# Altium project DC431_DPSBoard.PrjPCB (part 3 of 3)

## Sheet DC431_PowerStage.SchDoc
size 558 x 431 mm; Date: Not shown in title block; ApprovedBy: Not shown in title block; CheckedBy: Not shown in title block; Author: Not shown in title block; CompanyName: Not shown in title block; Engineer: Not shown in title block; Organization: Not shown in title block; Address1: Not shown in title block; Address2: Not shown in title block; Address3: Not shown in title block; Address4: Not shown in title block; DocumentNumber: 1; Revision: Use project parameter SCH_Rev; SheetNumber: 3; SheetTotal: 9; PageSetup: Record=PageOptions¦CenterHorizontal=True¦CenterVertical=True¦PrintScale=1.00¦XCorrection=1.00¦YCorrection=1.00¦PrintKind=0¦BorderSize=5000000¦LeftOffset=0¦BottomOffset=0¦Orientation=2¦PaperLength=1000¦PaperWidth=1000¦Scale=100¦PaperSource=15¦PrintQuality=600¦MediaType=1¦DitherType=10¦PaperKind=Letter¦PrintScaleMode=1
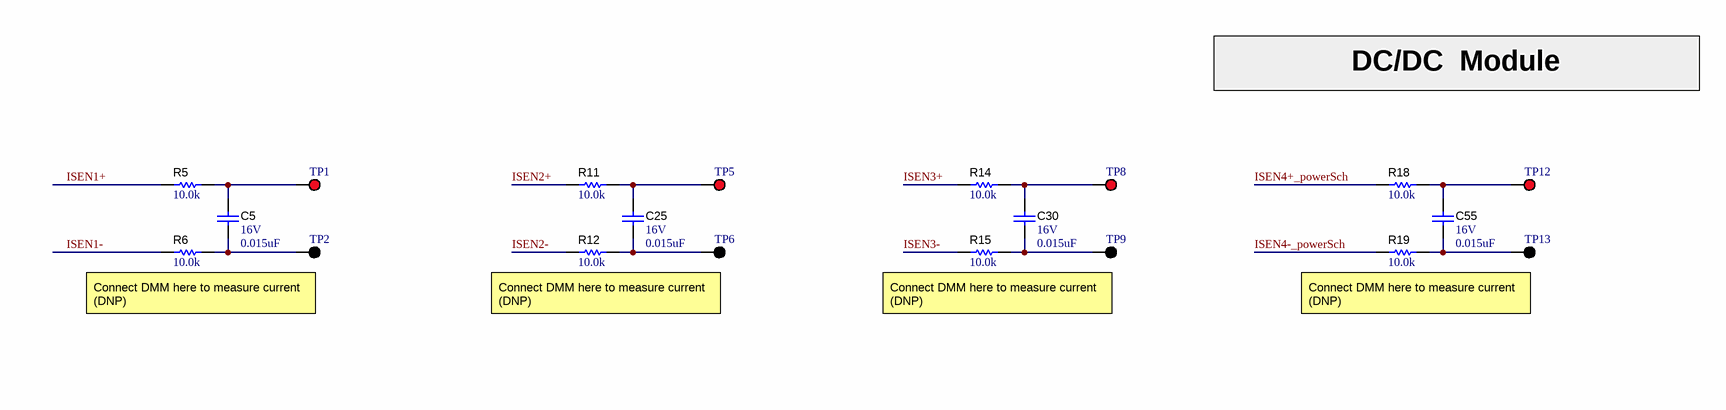
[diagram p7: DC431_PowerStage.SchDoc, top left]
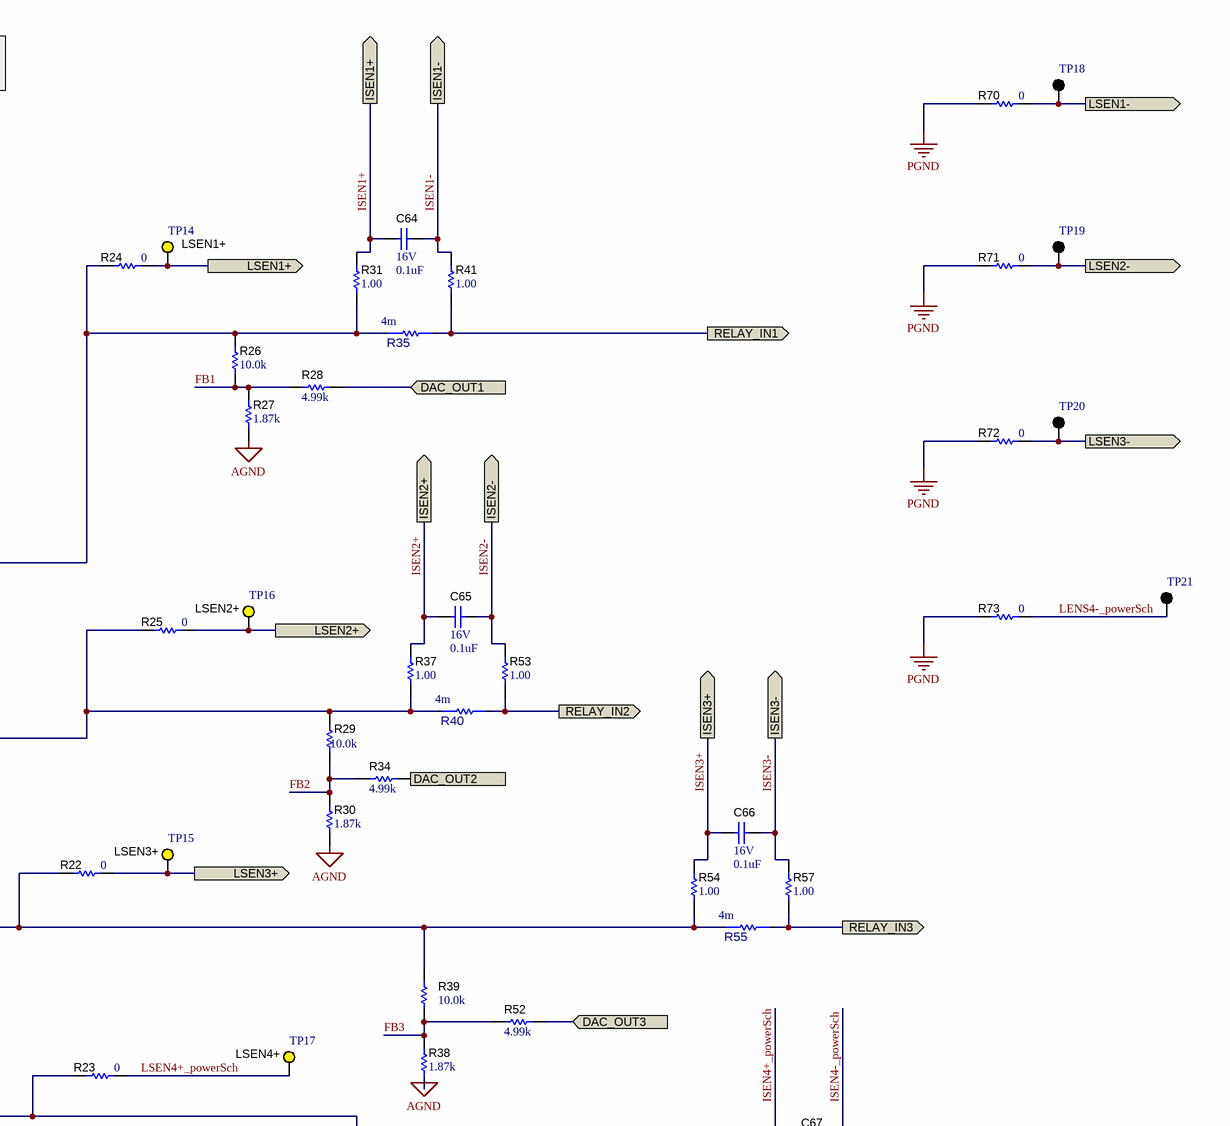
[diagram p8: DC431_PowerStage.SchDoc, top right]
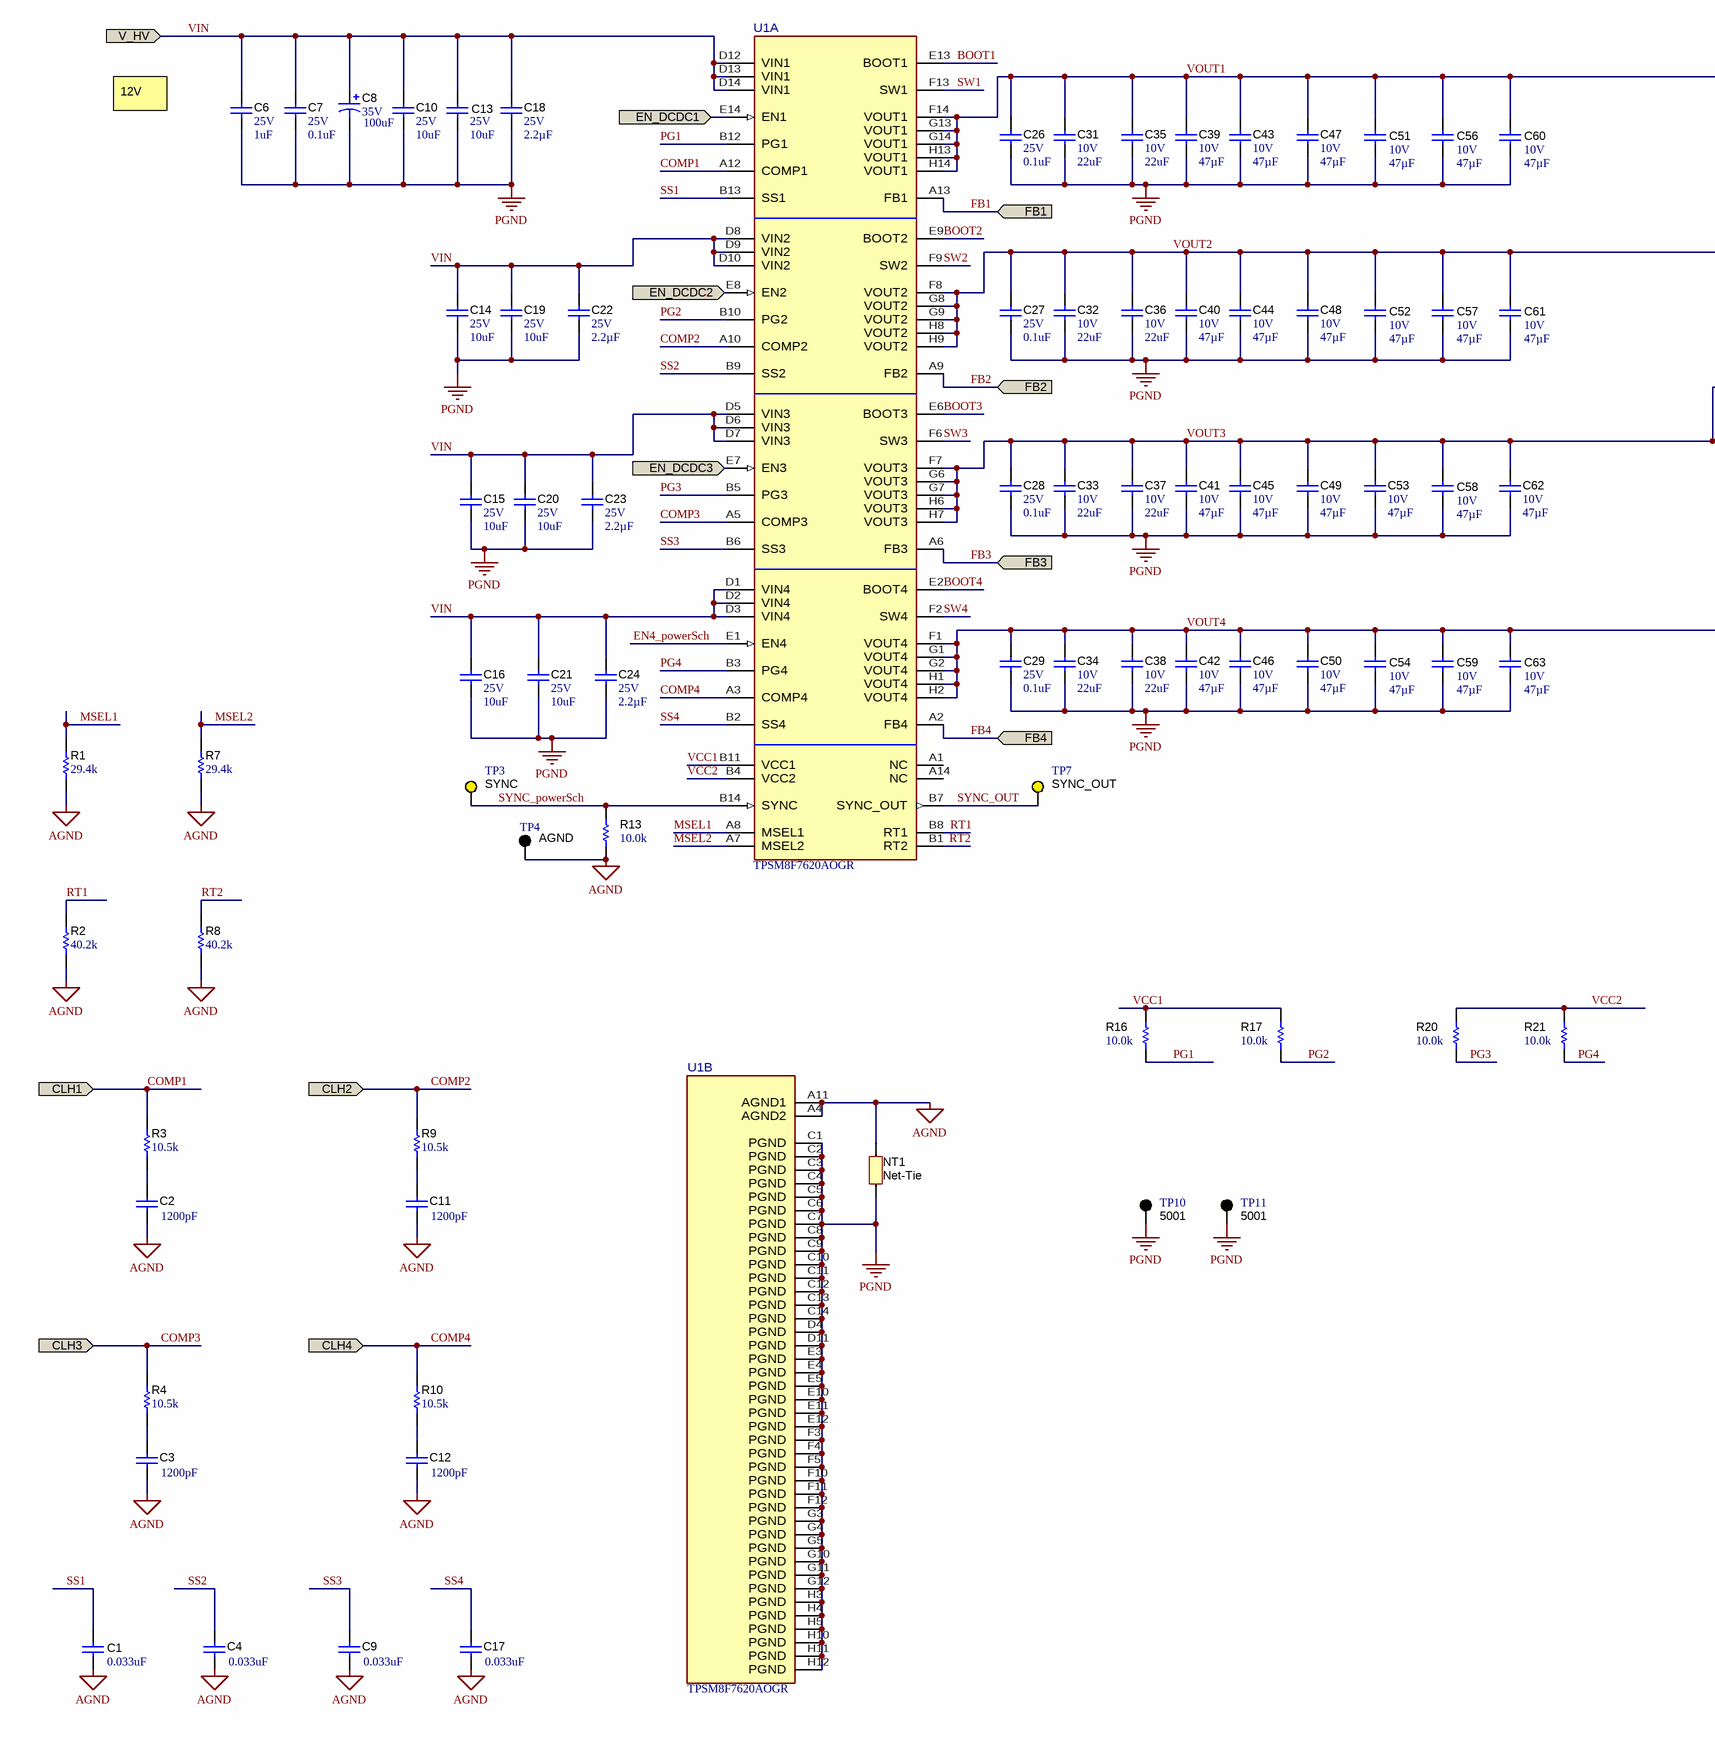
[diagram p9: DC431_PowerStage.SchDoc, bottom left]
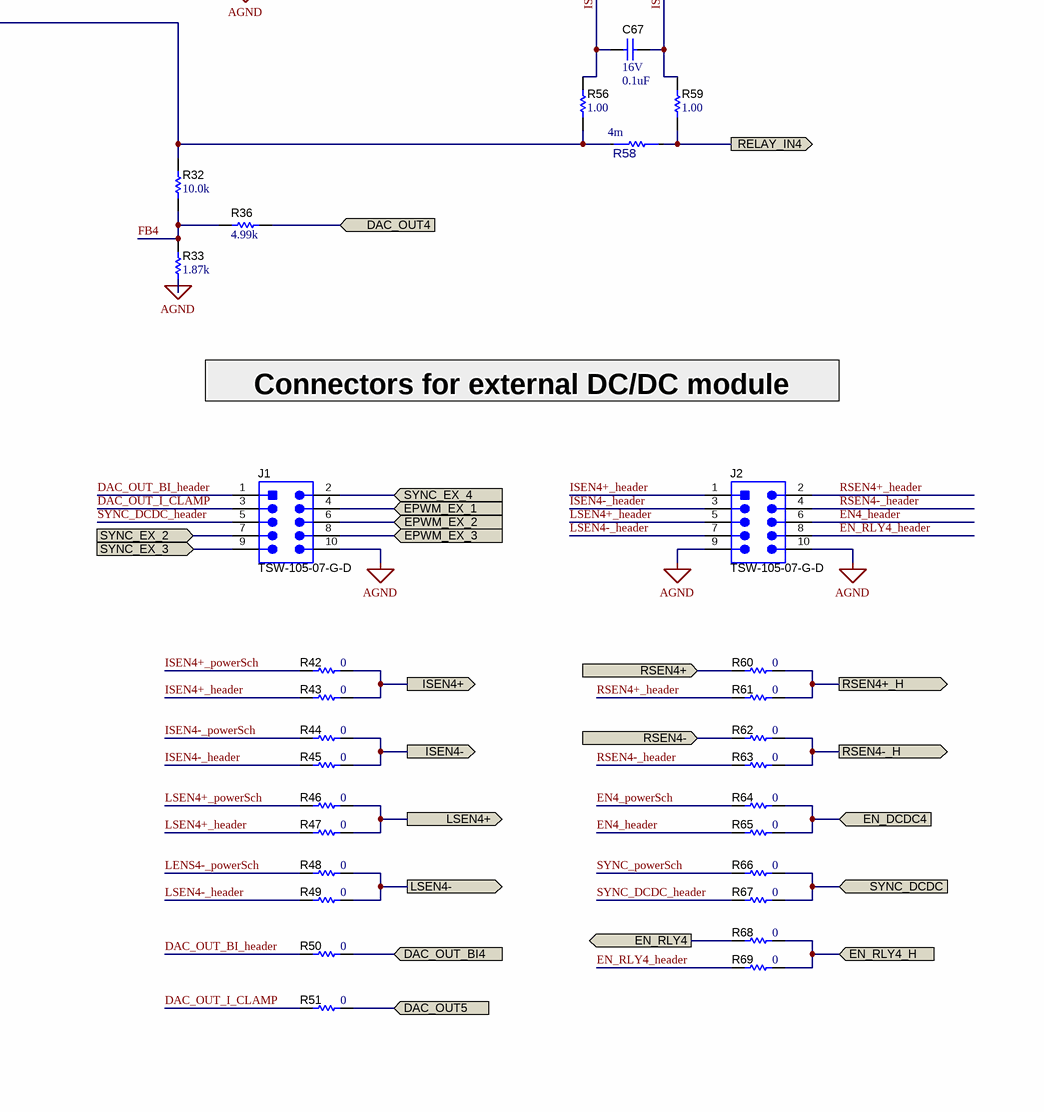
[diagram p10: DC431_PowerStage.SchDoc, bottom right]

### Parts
C1  ValueDisplayed: 0.033uF  [0402S]  (hidden comment: GRM155R71A333KA01D)
C2  ValueDisplayed: 1200pF  [0402S]  (hidden comment: GRM155R71H122KA01D)
C3  ValueDisplayed: 1200pF  [0402S]  (hidden comment: GRM155R71H122KA01D)
C4  ValueDisplayed: 0.033uF  [0402S]  (hidden comment: GRM155R71A333KA01D)
C5  VDC_V: 16V  ValueDisplayed: 0.015uF  [0402S]  (hidden comment: GRM155R71C153KA01D)
C6  VDC_V: 25V  ValueDisplayed: 1uF  [0603S]  (hidden comment: C1608X7R1E105K080AB)
C7  VDC_V: 25V  ValueDisplayed: 0.1uF  [0402S]  (hidden comment: GRM155R71E104KE14D)
C8  VDC_V: 35V  ValueDisplayed: 100uF  [SM_RADIAL_F]  (hidden comment: EEE-FK1V101P)
C9  ValueDisplayed: 0.033uF  [0402S]  (hidden comment: GRM155R71A333KA01D)
C10  VDC_V: 25V  ValueDisplayed: 10uF  [0805_HV]  (hidden comment: GRM21BC71E106KE11L)
C11  ValueDisplayed: 1200pF  [0402S]  (hidden comment: GRM155R71H122KA01D)
C12  ValueDisplayed: 1200pF  [0402S]  (hidden comment: GRM155R71H122KA01D)
C13  VDC_V: 25V  ValueDisplayed: 10uF  [0805_HV]  (hidden comment: GRM21BC71E106KE11L)
C14  VDC_V: 25V  ValueDisplayed: 10uF  [0805_HV]  (hidden comment: GRM21BC71E106KE11L)
C15  VDC_V: 25V  ValueDisplayed: 10uF  [0805_HV]  (hidden comment: GRM21BC71E106KE11L)
C16  VDC_V: 25V  ValueDisplayed: 10uF  [0805_HV]  (hidden comment: GRM21BC71E106KE11L)
C17  ValueDisplayed: 0.033uF  [0402S]  (hidden comment: GRM155R71A333KA01D)
C18  VDC_V: 25V  ValueDisplayed: 2.2µF  [0402S]  (hidden comment: GRM155R61E225ME15D)
C19  VDC_V: 25V  ValueDisplayed: 10uF  [0805_HV]  (hidden comment: GRM21BC71E106KE11L)
C20  VDC_V: 25V  ValueDisplayed: 10uF  [0805_HV]  (hidden comment: GRM21BC71E106KE11L)
C21  VDC_V: 25V  ValueDisplayed: 10uF  [0805_HV]  (hidden comment: GRM21BC71E106KE11L)
C22  VDC_V: 25V  ValueDisplayed: 2.2µF  [0402S]  (hidden comment: GRM155R61E225ME15D)
C23  VDC_V: 25V  ValueDisplayed: 2.2µF  [0402S]  (hidden comment: GRM155R61E225ME15D)
C24  VDC_V: 25V  ValueDisplayed: 2.2µF  [0402S]  (hidden comment: GRM155R61E225ME15D)
C25  VDC_V: 16V  ValueDisplayed: 0.015uF  [0402S]  (hidden comment: GRM155R71C153KA01D)
C26  VDC_V: 25V  ValueDisplayed: 0.1uF  [0402S]  (hidden comment: GRM155R71E104KE14D)
C27  VDC_V: 25V  ValueDisplayed: 0.1uF  [0402S]  (hidden comment: GRM155R71E104KE14D)
C28  VDC_V: 25V  ValueDisplayed: 0.1uF  [0402S]  (hidden comment: GRM155R71E104KE14D)
C29  VDC_V: 25V  ValueDisplayed: 0.1uF  [0402S]  (hidden comment: GRM155R71E104KE14D)
C30  VDC_V: 16V  ValueDisplayed: 0.015uF  [0402S]  (hidden comment: GRM155R71C153KA01D)
C31  VDC_V: 10V  ValueDisplayed: 22uF  [0805_HV]  (hidden comment: C2012X7S1A226M125AC)
C32  VDC_V: 10V  ValueDisplayed: 22uF  [0805_HV]  (hidden comment: C2012X7S1A226M125AC)
C33  VDC_V: 10V  ValueDisplayed: 22uF  [0805_HV]  (hidden comment: C2012X7S1A226M125AC)
C34  VDC_V: 10V  ValueDisplayed: 22uF  [0805_HV]  (hidden comment: C2012X7S1A226M125AC)
C35  VDC_V: 10V  ValueDisplayed: 22uF  [0805_HV]  (hidden comment: C2012X7S1A226M125AC)
C36  VDC_V: 10V  ValueDisplayed: 22uF  [0805_HV]  (hidden comment: C2012X7S1A226M125AC)
C37  VDC_V: 10V  ValueDisplayed: 22uF  [0805_HV]  (hidden comment: C2012X7S1A226M125AC)
C38  VDC_V: 10V  ValueDisplayed: 22uF  [0805_HV]  (hidden comment: C2012X7S1A226M125AC)
C39  VDC_V: 10V  ValueDisplayed: 47µF  [1210_270]  (hidden comment: LMK325B7476MM-PR)
C40  VDC_V: 10V  ValueDisplayed: 47µF  [1210_270]  (hidden comment: LMK325B7476MM-PR)
C41  VDC_V: 10V  ValueDisplayed: 47µF  [1210_270]  (hidden comment: LMK325B7476MM-PR)
C42  VDC_V: 10V  ValueDisplayed: 47µF  [1210_270]  (hidden comment: LMK325B7476MM-PR)
C43  VDC_V: 10V  ValueDisplayed: 47µF  [1210_270]  (hidden comment: LMK325B7476MM-PR)
C44  VDC_V: 10V  ValueDisplayed: 47µF  [1210_270]  (hidden comment: LMK325B7476MM-PR)
C45  VDC_V: 10V  ValueDisplayed: 47µF  [1210_270]  (hidden comment: LMK325B7476MM-PR)
C46  VDC_V: 10V  ValueDisplayed: 47µF  [1210_270]  (hidden comment: LMK325B7476MM-PR)
C47  VDC_V: 10V  ValueDisplayed: 47µF  [1210_270]  (hidden comment: LMK325B7476MM-PR)
C48  VDC_V: 10V  ValueDisplayed: 47µF  [1210_270]  (hidden comment: LMK325B7476MM-PR)
C49  VDC_V: 10V  ValueDisplayed: 47µF  [1210_270]  (hidden comment: LMK325B7476MM-PR)
C50  VDC_V: 10V  ValueDisplayed: 47µF  [1210_270]  (hidden comment: LMK325B7476MM-PR)
C51  Cap_F: 47µF  VDC_V: 10V  [1210_270]  (hidden comment: LMK325B7476MM-PR)
C52  Cap_F: 47µF  VDC_V: 10V  [1210_270]  (hidden comment: LMK325B7476MM-PR)
C53  VDC_V: 10V  ValueDisplayed: 47µF  [1210_270]  (hidden comment: LMK325B7476MM-PR)
C54  Cap_F: 47µF  VDC_V: 10V  [1210_270]  (hidden comment: LMK325B7476MM-PR)
C55  VDC_V: 16V  ValueDisplayed: 0.015uF  [0402S]  (hidden comment: GRM155R71C153KA01D)
C56  Cap_F: 47µF  VDC_V: 10V  [1210_270]  (hidden comment: LMK325B7476MM-PR)
C57  Cap_F: 47µF  VDC_V: 10V  [1210_270]  (hidden comment: LMK325B7476MM-PR)
C58  Cap_F: 47µF  VDC_V: 10V  [1210_270]  (hidden comment: LMK325B7476MM-PR)
C59  Cap_F: 47µF  VDC_V: 10V  [1210_270]  (hidden comment: LMK325B7476MM-PR)
C60  Cap_F: 47µF  VDC_V: 10V  [1210_270]  (hidden comment: LMK325B7476MM-PR)
C61  Cap_F: 47µF  VDC_V: 10V  [1210_270]  (hidden comment: LMK325B7476MM-PR)
C62  VDC_V: 10V  ValueDisplayed: 47µF  [1210_270]  (hidden comment: LMK325B7476MM-PR)
C63  Cap_F: 47µF  VDC_V: 10V  [1210_270]  (hidden comment: LMK325B7476MM-PR)
C64  VDC_V: 16V  ValueDisplayed: 0.1uF  [0402S]  (hidden comment: GRM155R61C104KA88D)
C65  VDC_V: 16V  ValueDisplayed: 0.1uF  [0402S]  (hidden comment: GRM155R61C104KA88D)
C66  VDC_V: 16V  ValueDisplayed: 0.1uF  [0402S]  (hidden comment: GRM155R61C104KA88D)
C67  VDC_V: 16V  ValueDisplayed: 0.1uF  [0402S]  (hidden comment: GRM155R61C104KA88D)
J1  TSW-105-07-G-D  [TSW-105-07-G-D]
J2  TSW-105-07-G-D  [TSW-105-07-G-D]
NT1  Net-Tie  [Net-Tie_10milWide_30milLong]  (net tie, no BOM)
R1  ValueDisplayed: 29.4k  [0402S]  (hidden comment: CRCW040229K4FKED)
R2  ValueDisplayed: 40.2k  [0402S]  (hidden comment: CRCW040240K2FKED)
R3  ValueDisplayed: 10.5k  [0402S]  (hidden comment: CRCW040210K5FKED)
R4  ValueDisplayed: 10.5k  [0402S]  (hidden comment: CRCW040210K5FKED)
R5  ValueDisplayed: 10.0k  [0603S]  (hidden comment: RT0603BRD0710KL)
R6  ValueDisplayed: 10.0k  [0603S]  (hidden comment: RT0603BRD0710KL)
R7  ValueDisplayed: 29.4k  [0402S]  (hidden comment: CRCW040229K4FKED)
R8  ValueDisplayed: 40.2k  [0402S]  (hidden comment: CRCW040240K2FKED)
R9  ValueDisplayed: 10.5k  [0402S]  (hidden comment: CRCW040210K5FKED)
R10  ValueDisplayed: 10.5k  [0402S]  (hidden comment: CRCW040210K5FKED)
R11  ValueDisplayed: 10.0k  [0603S]  (hidden comment: RT0603BRD0710KL)
R12  ValueDisplayed: 10.0k  [0603S]  (hidden comment: RT0603BRD0710KL)
R13  value 10.0k  [0402S]  (hidden comment: CRCW040210K0FKED)
R14  ValueDisplayed: 10.0k  [0603S]  (hidden comment: RT0603BRD0710KL)
R15  ValueDisplayed: 10.0k  [0603S]  (hidden comment: RT0603BRD0710KL)
R16  value 10.0k  [0402S]  (hidden comment: CRCW040210K0FKED)
R17  value 10.0k  [0402S]  (hidden comment: CRCW040210K0FKED)
R18  ValueDisplayed: 10.0k  [0603S]  (hidden comment: RT0603BRD0710KL)
R19  ValueDisplayed: 10.0k  [0603S]  (hidden comment: RT0603BRD0710KL)
R20  value 10.0k  [0402S]  (hidden comment: CRCW040210K0FKED)
R21  value 10.0k  [0402S]  (hidden comment: CRCW040210K0FKED)
R22  ValueDisplayed: 0  [0402S]  (hidden comment: CRCW04020000Z0ED)
R23  ValueDisplayed: 0  [0402S]  (hidden comment: CRCW04020000Z0ED)
R24  ValueDisplayed: 0  [0402S]  (hidden comment: CRCW04020000Z0ED)
R25  ValueDisplayed: 0  [0402S]  (hidden comment: CRCW04020000Z0ED)
R26  ValueDisplayed: 10.0k  [0402S]  (hidden comment: CRCW040210K0FKED)
R27  ValueDisplayed: 1.87k  [0402S]  (hidden comment: CRCW04021K87FKED)
R28  ValueDisplayed: 4.99k  [0402S]  (hidden comment: CRCW04024K99FKED)
R29  ValueDisplayed: 10.0k  [0402S]  (hidden comment: CRCW040210K0FKED)
R30  ValueDisplayed: 1.87k  [0402S]  (hidden comment: CRCW04021K87FKED)
R31  ValueDisplayed: 1.00  [0603S]  (hidden comment: CRCW06031R00FKEA)
R32  ValueDisplayed: 10.0k  [0402S]  (hidden comment: CRCW040210K0FKED)
R33  ValueDisplayed: 1.87k  [0402S]  (hidden comment: CRCW04021K87FKED)
R34  ValueDisplayed: 4.99k  [0402S]  (hidden comment: CRCW04024K99FKED)
R35  value 4m  [FP-TLRP3A20CR080FTE_2512-MFG]  (hidden comment: TLRP3A20CR004FTE)
R36  ValueDisplayed: 4.99k  [0402S]  (hidden comment: CRCW04024K99FKED)
R37  ValueDisplayed: 1.00  [0603S]  (hidden comment: CRCW06031R00FKEA)
R38  ValueDisplayed: 1.87k  [0402S]  (hidden comment: CRCW04021K87FKED)
R39  ValueDisplayed: 10.0k  [0402S]  (hidden comment: CRCW040210K0FKED)
R40  value 4m  [FP-TLRP3A20CR080FTE_2512-MFG]  (hidden comment: TLRP3A20CR004FTE)
R41  ValueDisplayed: 1.00  [0603S]  (hidden comment: CRCW06031R00FKEA)
R42  ValueDisplayed: 0  [0402S]  (hidden comment: CRCW04020000Z0ED)
R43  ValueDisplayed: 0  [0402S]  (hidden comment: CRCW04020000Z0ED)
R44  ValueDisplayed: 0  [0402S]  (hidden comment: CRCW04020000Z0ED)
R45  ValueDisplayed: 0  [0402S]  (hidden comment: CRCW04020000Z0ED)
R46  ValueDisplayed: 0  [0402S]  (hidden comment: CRCW04020000Z0ED)
R47  ValueDisplayed: 0  [0402S]  (hidden comment: CRCW04020000Z0ED)
R48  ValueDisplayed: 0  [0402S]  (hidden comment: CRCW04020000Z0ED)
R49  ValueDisplayed: 0  [0402S]  (hidden comment: CRCW04020000Z0ED)
R50  ValueDisplayed: 0  [0402S]  (hidden comment: CRCW04020000Z0ED)
R51  ValueDisplayed: 0  [0402S]  (hidden comment: CRCW04020000Z0ED)
R52  ValueDisplayed: 4.99k  [0402S]  (hidden comment: CRCW04024K99FKED)
R53  ValueDisplayed: 1.00  [0603S]  (hidden comment: CRCW06031R00FKEA)
R54  ValueDisplayed: 1.00  [0603S]  (hidden comment: CRCW06031R00FKEA)
R55  value 4m  [FP-TLRP3A20CR080FTE_2512-MFG]  (hidden comment: TLRP3A20CR004FTE)
R56  ValueDisplayed: 1.00  [0603S]  (hidden comment: CRCW06031R00FKEA)
R57  ValueDisplayed: 1.00  [0603S]  (hidden comment: CRCW06031R00FKEA)
R58  value 4m  [FP-TLRP3A20CR080FTE_2512-MFG]  (hidden comment: TLRP3A20CR004FTE)
R59  ValueDisplayed: 1.00  [0603S]  (hidden comment: CRCW06031R00FKEA)
R60  ValueDisplayed: 0  [0402S]  (hidden comment: CRCW04020000Z0ED)
R61  ValueDisplayed: 0  [0402S]  (hidden comment: CRCW04020000Z0ED)
R62  ValueDisplayed: 0  [0402S]  (hidden comment: CRCW04020000Z0ED)
R63  ValueDisplayed: 0  [0402S]  (hidden comment: CRCW04020000Z0ED)
R64  ValueDisplayed: 0  [0402S]  (hidden comment: CRCW04020000Z0ED)
R65  ValueDisplayed: 0  [0402S]  (hidden comment: CRCW04020000Z0ED)
R66  ValueDisplayed: 0  [0402S]  (hidden comment: CRCW04020000Z0ED)
R67  ValueDisplayed: 0  [0402S]  (hidden comment: CRCW04020000Z0ED)
R68  ValueDisplayed: 0  [0402S]  (hidden comment: CRCW04020000Z0ED)
R69  ValueDisplayed: 0  [0402S]  (hidden comment: CRCW04020000Z0ED)
R70  ValueDisplayed: 0  [0402S]  (hidden comment: CRCW04020000Z0ED)
R71  ValueDisplayed: 0  [0402S]  (hidden comment: CRCW04020000Z0ED)
R72  ValueDisplayed: 0  [0402S]  (hidden comment: CRCW04020000Z0ED)
R73  ValueDisplayed: 0  [0402S]  (hidden comment: CRCW04020000Z0ED)
TP1  5000  [Keystone5000]  (value not drawn)
TP2  5001  [Keystone5001]  (value not drawn)
TP3  SYNC  [Keystone5004]
TP4  AGND  [Keystone5001]
TP5  5000  [Keystone5000]  (value not drawn)
TP6  5001  [Keystone5001]  (value not drawn)
TP7  SYNC_OUT  [Keystone5004]
TP8  5000  [Keystone5000]  (value not drawn)
TP9  5001  [Keystone5001]  (value not drawn)
TP10  5001  [Keystone5001]
TP11  5001  [Keystone5001]
TP12  5000  [Keystone5000]  (value not drawn)
TP13  5001  [Keystone5001]  (value not drawn)
TP14  LSEN1+  [Keystone5004]
TP15  LSEN3+  [Keystone5004]
TP16  LSEN2+  [Keystone5004]
TP17  LSEN4+  [Keystone5004]
TP18  5001  [Keystone5001]  (value not drawn)
TP19  5001  [Keystone5001]  (value not drawn)
TP20  5001  [Keystone5001]  (value not drawn)
TP21  5001  [Keystone5001]  (value not drawn)
U1  TPSM8F7620AOGR  [APG0112A-MFG]  (parts A,B of 2)

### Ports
CLH1 (in), CLH2 (in), CLH3 (in), CLH4 (in), DAC_OUT1 (in), DAC_OUT2 (in), DAC_OUT3 (in), DAC_OUT4 (in), DAC_OUT5 (in), DAC_OUT_BI4 (in), EN_DCDC1 (in), EN_DCDC2 (in), EN_DCDC3 (in), EN_DCDC4 (in), EN_RLY4 (out), EN_RLY4_H (in), EPWM_EX_1 (in), EPWM_EX_2 (in), EPWM_EX_3 (in), FB1 (in), FB2 (in), FB3 (in), FB4 (in), ISEN1+ (out), ISEN1- (out), ISEN2+ (out), ISEN2- (out), ISEN3+ (out), ISEN3- (out), ISEN4+ (out), ISEN4- (out), LSEN1+ (out), LSEN1- (out), LSEN2+ (out), LSEN2- (out), LSEN3+ (out), LSEN3- (out), LSEN4+ (out), LSEN4- (out), RELAY_IN1 (out), RELAY_IN2 (out), RELAY_IN3 (out), RELAY_IN4 (out), RSEN4+ (in), RSEN4+_H (out), RSEN4- (in), RSEN4-_H (out), SYNC_DCDC (in), SYNC_EX_2 (in), SYNC_EX_3 (in), SYNC_EX_4 (in), V_HV (in)

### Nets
AGND: C1.2 C2.2 C3.2 C4.2 C9.2 C11.2 C12.2 C17.2 J1.10 J2.9 J2.10 NT1.2 R1.1 R2.1 R7.1 R8.1 R13.1 R27.1 R30.1 R33.1 R38.1 TP4.1 U1.A4(AGND2) U1.A11(AGND1)
PGND: C6.2 C7.2 C8.2(-) C10.2 C13.2 C14.2 C15.2 C16.2 C18.2 C19.2 C20.2 C21.2 C22.2 C23.2 C24.2 C26.2 C27.2 C28.2 C29.2 C31.2 C32.2 C33.2 C34.2 C35.2 C36.2 C37.2 C38.2 C39.2 C40.2 C41.2 C42.2 C43.2 C44.2 C45.2 C46.2 C47.2 C48.2 C49.2 C50.2 C51.2 C52.2 C53.2 C54.2 C56.2 C57.2 C58.2 C59.2 C60.2 C61.2 C62.2 C63.2 NT1.1 R70.1 R71.1 R72.1 R73.1 TP10.1 TP11.1 U1.C1(PGND) U1.C2(PGND) U1.C3(PGND) U1.C4(PGND) U1.C5(PGND) U1.C6(PGND) U1.C7(PGND) U1.C8(PGND) U1.C9(PGND) U1.C10(PGND) U1.C11(PGND) U1.C12(PGND) U1.C13(PGND) U1.C14(PGND) U1.D4(PGND) U1.D11(PGND) U1.E3(PGND) U1.E4(PGND) U1.E5(PGND) U1.E10(PGND) U1.E11(PGND) U1.E12(PGND) U1.F3(PGND) U1.F4(PGND) U1.F5(PGND) U1.F10(PGND) U1.F11(PGND) U1.F12(PGND) U1.G3(PGND) U1.G4(PGND) U1.G5(PGND) U1.G10(PGND) U1.G11(PGND) U1.G12(PGND) U1.H3(PGND) U1.H4(PGND) U1.H5(PGND) U1.H10(PGND) U1.H11(PGND) U1.H12(PGND)
AINM4: R62.2 R63.2 ; port RSEN4-_H
AINM8: R44.2 R45.2 ; port ISEN4-
AINM9: R70.2 TP18.1 ; port LSEN1-
AINM10: R71.2 TP19.1 ; port LSEN2-
AINM11: R72.2 TP20.1 ; port LSEN3-
AINM12: R48.2 R49.2 ; port LSEN4-
AINP4: R60.2 R61.2 ; port RSEN4+_H
AINP8: R42.2 R43.2 ; port ISEN4+
AINP9: R24.2 TP14.1 ; port LSEN1+
AINP10: R25.2 TP16.1 ; port LSEN2+
AINP11: R22.2 TP15.1 ; port LSEN3+
AINP12: R46.2 R47.2 ; port LSEN4+
BOOT1: U1.E13(BOOT1)
BOOT2: U1.E9(BOOT2)
BOOT3: U1.E6(BOOT3)
BOOT4: U1.E2(BOOT4)
COMP1: R3.2 U1.A12(COMP1) ; port CLH1
COMP2: R9.2 U1.A10(COMP2) ; port CLH2
COMP3: R4.2 U1.A5(COMP3) ; port CLH3
COMP4: R10.2 U1.A3(COMP4) ; port CLH4
DAC_CH4: R36.2 ; port DAC_OUT4
DAC_OUT1: R28.2 ; port DAC_OUT1
DAC_OUT2: R34.2 ; port DAC_OUT2
DAC_OUT3: R52.2 ; port DAC_OUT3
DAC_OUT5: R51.2 ; port DAC_OUT5
DAC_OUT_BI4: R50.2 ; port DAC_OUT_BI4
DAC_OUT_BI_header: J1.1 R50.1
DAC_OUT_I_CLAMP: J1.3 R51.1
EN4_header: J2.6 R65.1
EN4_powerSch: R64.1 U1.E1(EN4)
EN_DCDC1: U1.E14(EN1) ; port EN_DCDC1
EN_DCDC2: U1.E8(EN2) ; port EN_DCDC2
EN_DCDC3: U1.E7(EN3) ; port EN_DCDC3
EN_DCDC4: R64.2 R65.2 ; port EN_DCDC4
EN_RLY4: R68.1 ; port EN_RLY4
EN_RLY4_H: R68.2 R69.2 ; port EN_RLY4_H
EN_RLY4_header: J2.8 R69.1
EPWM_EX_1: J1.4 ; port EPWM_EX_1
EPWM_EX_2: J1.6 ; port EPWM_EX_2
EPWM_EX_3: J1.8 ; port EPWM_EX_3
FB1: R26.1 R27.2 R28.1 U1.A13(FB1) ; port FB1
FB2: R29.1 R30.2 R34.1 U1.A9(FB2) ; port FB2
FB3: R38.2 R39.1 R52.1 U1.A6(FB3) ; port FB3
FB4: R32.1 R33.2 R36.1 U1.A2(FB4) ; port FB4
ISEN1+: C64.2 R5.2 R31.1 ; port ISEN1+  [project net AINP5]
ISEN1-: C64.1 R6.2 R41.1 ; port ISEN1-  [project net AINM5]
ISEN2+: C65.2 R11.2 R37.1 ; port ISEN2+  [project net AINP6]
ISEN2-: C65.1 R12.2 R53.1 ; port ISEN2-  [project net AINM6]
ISEN3+: C66.2 R14.2 R54.1 ; port ISEN3+  [project net AINP7]
ISEN3-: C66.1 R15.2 R57.1 ; port ISEN3-  [project net AINM7]
ISEN4+_header: J2.1 R43.1
ISEN4+_powerSch: C67.2 R18.2 R42.1 R56.1
ISEN4-_header: J2.3 R45.1
ISEN4-_powerSch: C67.1 R19.2 R44.1 R59.1
LENS4-_powerSch: R48.1 R73.2 TP21.1
LSEN4+_header: J2.5 R47.1
LSEN4+_powerSch: R23.2 R46.1 TP17.1
LSEN4-_header: J2.7 R49.1
MSEL1: R1.2 U1.A8(MSEL1)
MSEL2: R7.2 U1.A7(MSEL2)
PG1: R16.1 U1.B12(PG1)
PG2: R17.1 U1.B10(PG2)
PG3: R20.1 U1.B5(PG3)
PG4: R21.1 U1.B3(PG4)
RELAY_IN1: R35.2 R41.2 ; port RELAY_IN1
RELAY_IN2: R40.2 R53.2 ; port RELAY_IN2
RELAY_IN3: R55.2 R57.2 ; port RELAY_IN3
RELAY_IN4: R58.2 R59.2 ; port RELAY_IN4
REMSN4: R62.1 ; port RSEN4-
REMSP4: R60.1 ; port RSEN4+
RSEN4+_header: J2.2 R61.1
RSEN4-_header: J2.4 R63.1
RT1: R2.2 U1.B8(RT1)
RT2: R8.2 U1.B1(RT2)
SS1: C1.1 U1.B13(SS1)
SS2: C4.1 U1.B9(SS2)
SS3: C9.1 U1.B6(SS3)
SS4: C17.1 U1.B2(SS4)
SW1: U1.F13(SW1)
SW2: U1.F9(SW2)
SW3: U1.F6(SW3)
SW4: U1.F2(SW4)
SYNC_DCDC: R66.2 R67.2 ; port SYNC_DCDC
SYNC_DCDC_header: J1.5 R67.1
SYNC_EX_2: J1.7 ; port SYNC_EX_2
SYNC_EX_3: J1.9 ; port SYNC_EX_3
SYNC_EX_4: J1.2 ; port SYNC_EX_4
SYNC_OUT: TP7.1 U1.B7(SYNC_OUT)
SYNC_powerSch: R13.2 R66.1 TP3.1 U1.B14(SYNC)
VCC1: R16.2 R17.2 U1.B11(VCC1)
VCC2: R20.2 R21.2 U1.B4(VCC2)
VIN: C6.1 C7.1 C8.1(+) C10.1 C13.1 C14.1 C15.1 C16.1 C18.1 C19.1 C20.1 C21.1 C22.1 C23.1 C24.1 U1.D1(VIN4) U1.D2(VIN4) U1.D3(VIN4) U1.D5(VIN3) U1.D6(VIN3) U1.D7(VIN3) U1.D8(VIN2) U1.D9(VIN2) U1.D10(VIN2) U1.D12(VIN1) U1.D13(VIN1) U1.D14(VIN1) ; port V_HV  [project net V_HV]
VOUT1: C26.1 C31.1 C35.1 C39.1 C43.1 C47.1 C51.1 C56.1 C60.1 R24.1 R26.2 R31.2 R35.1 U1.F14(VOUT1) U1.G13(VOUT1) U1.G14(VOUT1) U1.H13(VOUT1) U1.H14(VOUT1)
VOUT2: C27.1 C32.1 C36.1 C40.1 C44.1 C48.1 C52.1 C57.1 C61.1 R25.1 R29.2 R37.2 R40.1 U1.F8(VOUT2) U1.G8(VOUT2) U1.G9(VOUT2) U1.H8(VOUT2) U1.H9(VOUT2)
VOUT3: C28.1 C33.1 C37.1 C41.1 C45.1 C49.1 C53.1 C58.1 C62.1 R22.1 R39.2 R54.2 R55.1 U1.F7(VOUT3) U1.G6(VOUT3) U1.G7(VOUT3) U1.H6(VOUT3) U1.H7(VOUT3)
VOUT4: C29.1 C34.1 C38.1 C42.1 C46.1 C50.1 C54.1 C59.1 C63.1 R23.1 R32.2 R56.2 R58.1 U1.F1(VOUT4) U1.G1(VOUT4) U1.G2(VOUT4) U1.H1(VOUT4) U1.H2(VOUT4)
NetC2_1: C2.1 R3.1
NetC3_1: C3.1 R4.1
NetC5_1: C5.1 R5.1 TP1.1
NetC5_2: C5.2 R6.1 TP2.1
NetC11_1: C11.1 R9.1
NetC12_1: C12.1 R10.1
NetC25_1: C25.1 R11.1 TP5.1
NetC25_2: C25.2 R12.1 TP6.1
NetC30_1: C30.1 R14.1 TP8.1
NetC30_2: C30.2 R15.1 TP9.1
NetC55_1: C55.1 R18.1 TP12.1
NetC55_2: C55.2 R19.1 TP13.1

Not connected (* = marked no-connect by the designer): U1 A1(NC) A14(NC)

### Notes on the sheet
- DC/DC  Module
- Connect DMM here to measure current
  (DNP)
- 12V
- Connectors for external DC/DC module

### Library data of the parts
C1 C4 C9 C17 = CMP-0006632-2: CAP, CERM, 0.033 uF, 10 V, +/- 10%, X7R, 0402; Manufacturer: MuRata; VDC_V: 10V; TaMax_C: 125°C; AEC Category: Q200; Value1: Unknown; SizeAreaWB_mm2: 3; Cap_F: 33nF; U/M: EA; SizeX_mm: 1; SizeZ_mm: 0.6; Cap_Case: 0402; TaMin_C: -55°C; Polarized: N; SizeY_mm: 0.5
C2 C3 C11 C12 = CMP-0006676-2: CAP, CERM, 1200 pF, 50 V, +/- 10%, X7R, 0402; Manufacturer: MuRata; VDC_V: 50V; TaMax_C: 125°C; AEC Category: Q200; Value1: Unknown; SizeAreaWB_mm2: 3; Cap_F: 1.2nF; U/M: EA; Value: 1200pF; SizeX_mm: 1; SizeZ_mm: 0.6; Cap_Case: 0402; TaMin_C: -55°C; Polarized: N; SizeY_mm: 0.5
C5 C25 C30 C55 = CMP-0006644-2: CAP, CERM, 0.015 uF, 16 V, +/- 10%, X7R, 0402; Manufacturer: MuRata; TaMin_C: -55°C; Polarized: N; SizeAreaWB_mm2: 3; Value1: Unknown; U/M: EA; TaMax_C: 125°C; SizeZ_mm: 0.6; SizeX_mm: 1; SizeY_mm: 0.5; Cap_Case: 0402; Cap_F: 15nF; AEC Category: Q200
C6 = CMP-0007040-4: CAP, CERM, 1 uF, 25 V, +/- 10%, X7R, 0603; Manufacturer: TDK; TaMin_C: -55°C; Polarized: N; SizeAreaWB_mm2: 4.68; U/M: EA; Value: 1uF; TaMax_C: 125°C; SizeZ_mm: 1; SizeX_mm: 1.6; SizeY_mm: 0.8; Cap_Case: 0603; SizeArea_mm2: 1.28; Cap_F: 1µF; AEC Category: Q200; Value1: Unknown
C7 = CMP-0006659-2: CAP, CERM, 0.1 uF, 25 V, +/- 10%, X7R, 0402; Manufacturer: MuRata; TaMin_C: -55°C; Polarized: N; SizeAreaWB_mm2: 3; U/M: EA; Value: 0.1uF; TaMax_C: 125°C; SizeZ_mm: 0.6; SizeX_mm: 1; SizeY_mm: 0.5; Cap_Case: 0402; Cap_F: 100nF; AEC Category: Q200; Value1: Unknown
C8 = CMP-0010723-1: CAP, AL, 100 uF, 35 V, +/- 20%, 0.16 ohm, AEC-Q200 Grade 2, SMD; Manufacturer: Panasonic; TaMin_C: -55°C; ESR_ohm: 0.16; Polarized: Y; SizeAreaWB_mm2: 123.6; U/M: EA; Value: 100uF; TaMax_C: 105°C; SizeZ_mm: 10.2; SizeX_mm: 10; SizeY_mm: 8.3; Cap_Case: F; SizeArea_mm2: 83; CompType: Capacitor; Cap_F: 100µF; IRMS_A: 600mA; AEC Grade: 2; AEC Category: Q200
C10 C13-C16 C19-C21 = CMP-0008262-2: CAP, CERM, 10 uF, 25 V, +/- 10%, X7S, 0805; Manufacturer: MuRata; TaMin_C: -55°C; Polarized: N; SizeAreaWB_mm2: 6.75; Value1: Unknown; U/M: EA; Value: 10uF; TaMax_C: 125°C; SizeZ_mm: 1.45; SizeX_mm: 2; SizeY_mm: 1.25; Cap_Case: 0805; SizeArea_mm2: 2.5; Cap_F: 10µF; AEC Category: Q200
C18 C22-C24 = CMP-0081010-1: CAP, CERM, 2.2 µF, 25 V,+/- 20%, X5R, 0402; Manufacturer: MuRata; TaMin_C: -55°C; Polarized: N; SizeAreaWB_mm2: 3; U/M: EA; Value: 2.2uF; TaMax_C: 85°C; SizeZ_mm: 0.6; SizeX_mm: 1; SizeY_mm: 0.5; Cap_Case: 0402; AEC Category: Q200
C26-C29 = CMP-0006659-2: CAP, CERM, 0.1 uF, 25 V, +/- 10%, X7R, 0402; Manufacturer: MuRata; TaMin_C: -55°C; Polarized: N; SizeAreaWB_mm2: 3; Value1: Unknown; U/M: EA; Value: 0.1uF; TaMax_C: 125°C; SizeZ_mm: 0.6; SizeX_mm: 1; SizeY_mm: 0.5; Cap_Case: 0402; Cap_F: 100nF; AEC Category: Q200
C31-C38 = CMP-0007890-2: CAP, CERM, 22 uF, 10 V, +/- 20%, X7S, 0805; Manufacturer: TDK; TaMin_C: -55°C; ESR_ohm: 2.05m; Polarized: N; SizeAreaWB_mm2: 6.75; Value1: 0.00205 ohm; U/M: EA; Value: 22uF; TaMax_C: 125°C; SizeZ_mm: 1.45; SizeX_mm: 2; SizeY_mm: 1.25; Cap_Case: 0805; SizeArea_mm2: 2.5; Cap_F: 22µF; IRMS_A: 4.5559A; AEC Category: Q200
C39-C50 C53 C62 = CMP-0082099-1: CAP, CERM, 47 µF, 10 V,+/- 20%, X7R, 1210; Manufacturer: Taiyo Yuden; TaMin_C: -55°C; ESR_ohm: 1m; Polarized: N; SizeAreaWB_mm2: 14.7; Value1: 0.001 ohm; U/M: EA; Value: 47uF; TaMax_C: 125°C; SizeZ_mm: 2.7; SizeX_mm: 3.2; SizeY_mm: 2.5; Cap_Case: 1210; SizeArea_mm2: 8; IRMS_A: 4.25A; AEC Category: Q200
C51 C52 C54 C56-C61 C63 = CMP-0082099-1: CAP, CERM, 47 µF, 10 V,+/- 20%, X7R, 1210; Manufacturer: Taiyo Yuden; AEC Qualified: N; SizeZ_mm: 2.7; TaMin_C: -55°C; ESR_ohm: 1m; SizeAreaWB_mm2: 14.7; Value1: 0.001 ohm; U/M: EA; Value: 47uF; TaMax_C: 125°C; SizeX_mm: 3.2; SizeY_mm: 2.5; Cap_Case: 1210; SizeArea_mm2: 8; IRMS_A: 4.25A; AEC Category: Q200
C64-C67 = CMP-0006591-2: CAP, CERM, 0.1 uF, 16 V, +/- 10%, X5R, 0402; Manufacturer: MuRata; TaMin_C: -55°C; Polarized: N; SizeAreaWB_mm2: 3; Value1: Unknown; U/M: EA; Value: 0.1uF; TaMax_C: 85°C; SizeZ_mm: 0.6; SizeX_mm: 1; SizeY_mm: 0.5; Cap_Case: 0402; Cap_F: 100nF; AEC Category: Q200
J1 J2 = CMP-0075410-2: Header, 100mil, 5x2, Gold, TH; Manufacturer: Samtec; Pitch_mm: 2.54; Cert_VDE: N; Gender: Male; Cert_CSA: Y; Voltage_V: 550V; Green_REACh: Passed; Current_A: 6.3A; Green_Lifecycle: Active; Row_Count: 2
NT1 = CMP-0078142-6: Single point connection between nets.
R1 R7 = CMP-0026225-2: RES, 29.4 k, 1%, 0.063 W, AEC-Q200 Grade 0, 0402; Manufacturer: Vishay-Dale; Power_W: 63mW; TempCo: 100 ppm/C; Value_Code: 29k4; Value: 29.4k; EIA_Code: E96; SizeX_mm: 1; SizeY_mm: 0.5; SizeZ_mm: 0.6; Value2: 0.063W; AEC Qualified: Y; VDC_V: 50V; AEC Category: Q200; AEC Grade: 0
R2 R8 = CMP-0026367-2: RES, 40.2 k, 1%, 0.063 W, AEC-Q200 Grade 0, 0402; Manufacturer: Vishay-Dale; Power_W: 63mW; TempCo: 100 ppm/C; Value_Code: 40k2; Value: 40.2k; EIA_Code: E96; SizeX_mm: 1; SizeY_mm: 0.5; SizeZ_mm: 0.6; Value2: 0.063W; AEC Qualified: Y; VDC_V: 50V; AEC Category: Q200; AEC Grade: 0
R3 R4 R9 R10 = CMP-0025960-3: RES, 10.5 k, 1%, 0.063 W, AEC-Q200 Grade 0, 0402; Manufacturer: Vishay-Dale; Power_W: 63mW; TempCo: 100 ppm/C; Value_Code: 10k5; Value: 10.5k; EIA_Code: E96; SizeX_mm: 1; SizeY_mm: 0.5; SizeZ_mm: 0.6; Value2: 0.063W; AEC Qualified: Y; VDC_V: 50V; AEC Category: Q200; AEC Grade: 0
R5 R6 R11 R12 R14 R15 R18 R19 = CMP-0023653-3: RES, 10.0 k, 0.1%, 0.1 W, 0603; Manufacturer: Yageo America; Power_W: 100mW; TempCo: 25 ppm/C; Value_Code: 10k0; Value: 10.0k; EIA_Code: E192; Res_ohm: 10k; SizeX_mm: 1.6; SizeY_mm: 0.8; SizeZ_mm: 1; Value2: 0.1W; SizeArea_mm2: 1.28; VDC_V: 75V; AEC Category: Q200; U/M: EA
R13 R16 R17 R20 R21 = CMP-0025958-3: RES, 10.0 k, 1%, 0.063 W, AEC-Q200 Grade 0, 0402; Manufacturer: Vishay-Dale; VDC_V: 50V; SizeZ_mm: 0.6; Res_ohm: 10k; TempCo: 100 ppm/C; Power_W: 63mW; AEC Qualified: Y; Value_Code: 10k0; EIA_Code: E96; SizeX_mm: 1; SizeY_mm: 0.5; Value2: 0.063W; AEC Category: Q200; AEC Grade: 0
R22-R25 R42-R51 R60-R73 = CMP-0026822-3: RES, 0, 5%, 0.063 W, AEC-Q200 Grade 0, 0402; Manufacturer: Vishay-Dale; Value: 0; Value_Code: 0000; Power_W: 63mW; Value2: 0.063W; VDC_V: 50V; TempCo: 200 ppm/C; SizeArea_mm2: 0.5; SizeX_mm: 1; SizeZ_mm: 0.6; EIA_Code: E24; AEC Category: Q200; AEC Qualified: Y
R26 R29 R32 R39 = CMP-0025958-3: RES, 10.0 k, 1%, 0.063 W, AEC-Q200 Grade 0, 0402; Manufacturer: Vishay-Dale; Power_W: 63mW; TempCo: 100 ppm/C; Value_Code: 10k0; Value: 10.0k; EIA_Code: E96; Res_ohm: 10k; SizeX_mm: 1; SizeY_mm: 0.5; SizeZ_mm: 0.6; Value2: 0.063W; AEC Qualified: Y; VDC_V: 50V; AEC Category: Q200; AEC Grade: 0
R27 R30 R33 R38 = CMP-0026097-2: RES, 1.87 k, 1%, 0.063 W, AEC-Q200 Grade 0, 0402; Manufacturer: Vishay-Dale; Power_W: 63mW; TempCo: 100 ppm/C; Value_Code: 1k87; Value: 1.87k; EIA_Code: E96; SizeX_mm: 1; SizeY_mm: 0.5; SizeZ_mm: 0.6; Value2: 0.063W; AEC Qualified: Y; VDC_V: 50V; AEC Category: Q200; AEC Grade: 0
R28 R34 R36 R52 = CMP-0026414-2: RES, 4.99 k, 1%, 0.063 W, AEC-Q200 Grade 0, 0402; Manufacturer: Vishay-Dale; Power_W: 63mW; TempCo: 100 ppm/C; Value_Code: 4k99; Value: 4.99k; EIA_Code: E96; SizeX_mm: 1; SizeY_mm: 0.5; SizeZ_mm: 0.6; Value2: 0.063W; AEC Qualified: Y; VDC_V: 50V; AEC Category: Q200; AEC Grade: 0
R31 R37 R41 R53 R54 R56 R57 R59 = CMP-0022170-4: RES, 1.00, 1%, 0.1 W, AEC-Q200 Grade 0, 0603; Manufacturer: Vishay-Dale; Power_W: 100mW; TempCo: 100 ppm/C; Value_Code: 1R00; Value: 1.00; EIA_Code: E96; Res_ohm: 1; SizeX_mm: 1.6; SizeY_mm: 0.8; Value2: 0.1W; SizeArea_mm2: 1.28; AEC Qualified: Y; VDC_V: 75V; AEC Category: Q200; AEC Grade: 0
R35 R40 R55 R58 = CMP-0126009-1: 4 mOhms ±1% 2W Chip Resistor 2512 (6432 Metric) Anti-Sulfur, Automotive AEC-Q200, Current Sense Metal Element; Manufacturer: TE Connectivity; AEC Grade: Grade 0; AEC Qualified: Yes; SizeZ_mm: 0.9mm; TempCo: 25ppm/°C
TP1 TP5 TP8 TP12 = CMP-0055137-2: Test Point, Miniature, Red, TH; Manufacturer: Keystone Electronics; Green_REACh: Passed; Green_Lifecycle: Active; ContactFinish: Silver; CNHeader: FALSE; CT: TRUE
TP2 TP4 TP6 TP9 TP13 = CMP-0055138-2: Test Point, Miniature, Black, TH; Manufacturer: Keystone Electronics; ContactFinish: Silver; CNHeader: FALSE; Green_Lifecycle: Active; Green_REACh: Passed; CT: TRUE
TP3 TP7 TP14-TP17 = CMP-0055141-2: Test Point, Miniature, Yellow, TH; Manufacturer: Keystone Electronics; CNHeader: FALSE; Green_Lifecycle: Active; Green_REACh: Passed; ContactFinish: Silver; CT: TRUE
TP10 TP11 TP18-TP21 = CMP-0055138-2: Test Point, Miniature, Black, TH; Manufacturer: Keystone Electronics; CNHeader: FALSE; ContactFinish: Silver; Green_REACh: Passed; Green_Lifecycle: Active; CT: TRUE
U1 = CMP-0123459-1: Manufacturer: Texas Instruments; SizeZ_mm: 2.5mm; Standoff Height: 0.35mm

## Sheet DC431_Clamp_Optional.SchDoc
size 431 x 279 mm; Date: Not shown in title block; ApprovedBy: Not shown in title block; CheckedBy: Not shown in title block; Author: Not shown in title block; CompanyName: Not shown in title block; Engineer: Not shown in title block; Organization: Not shown in title block; Address1: Not shown in title block; Address2: Not shown in title block; Address3: Not shown in title block; Address4: Not shown in title block; DocumentNumber: 1; Revision: Use project parameter SCH_Rev; SheetNumber: 5; SheetTotal: 9; PageSetup: Record=PageOptions¦CenterHorizontal=True¦CenterVertical=True¦PrintScale=1.00¦XCorrection=1.00¦YCorrection=1.00¦PrintKind=0¦BorderSize=5000000¦LeftOffset=0¦BottomOffset=0¦Orientation=2¦PaperLength=1000¦PaperWidth=1000¦Scale=100¦PaperSource=15¦PrintQuality=600¦MediaType=1¦DitherType=10¦PaperKind=Letter¦PrintScaleMode=1
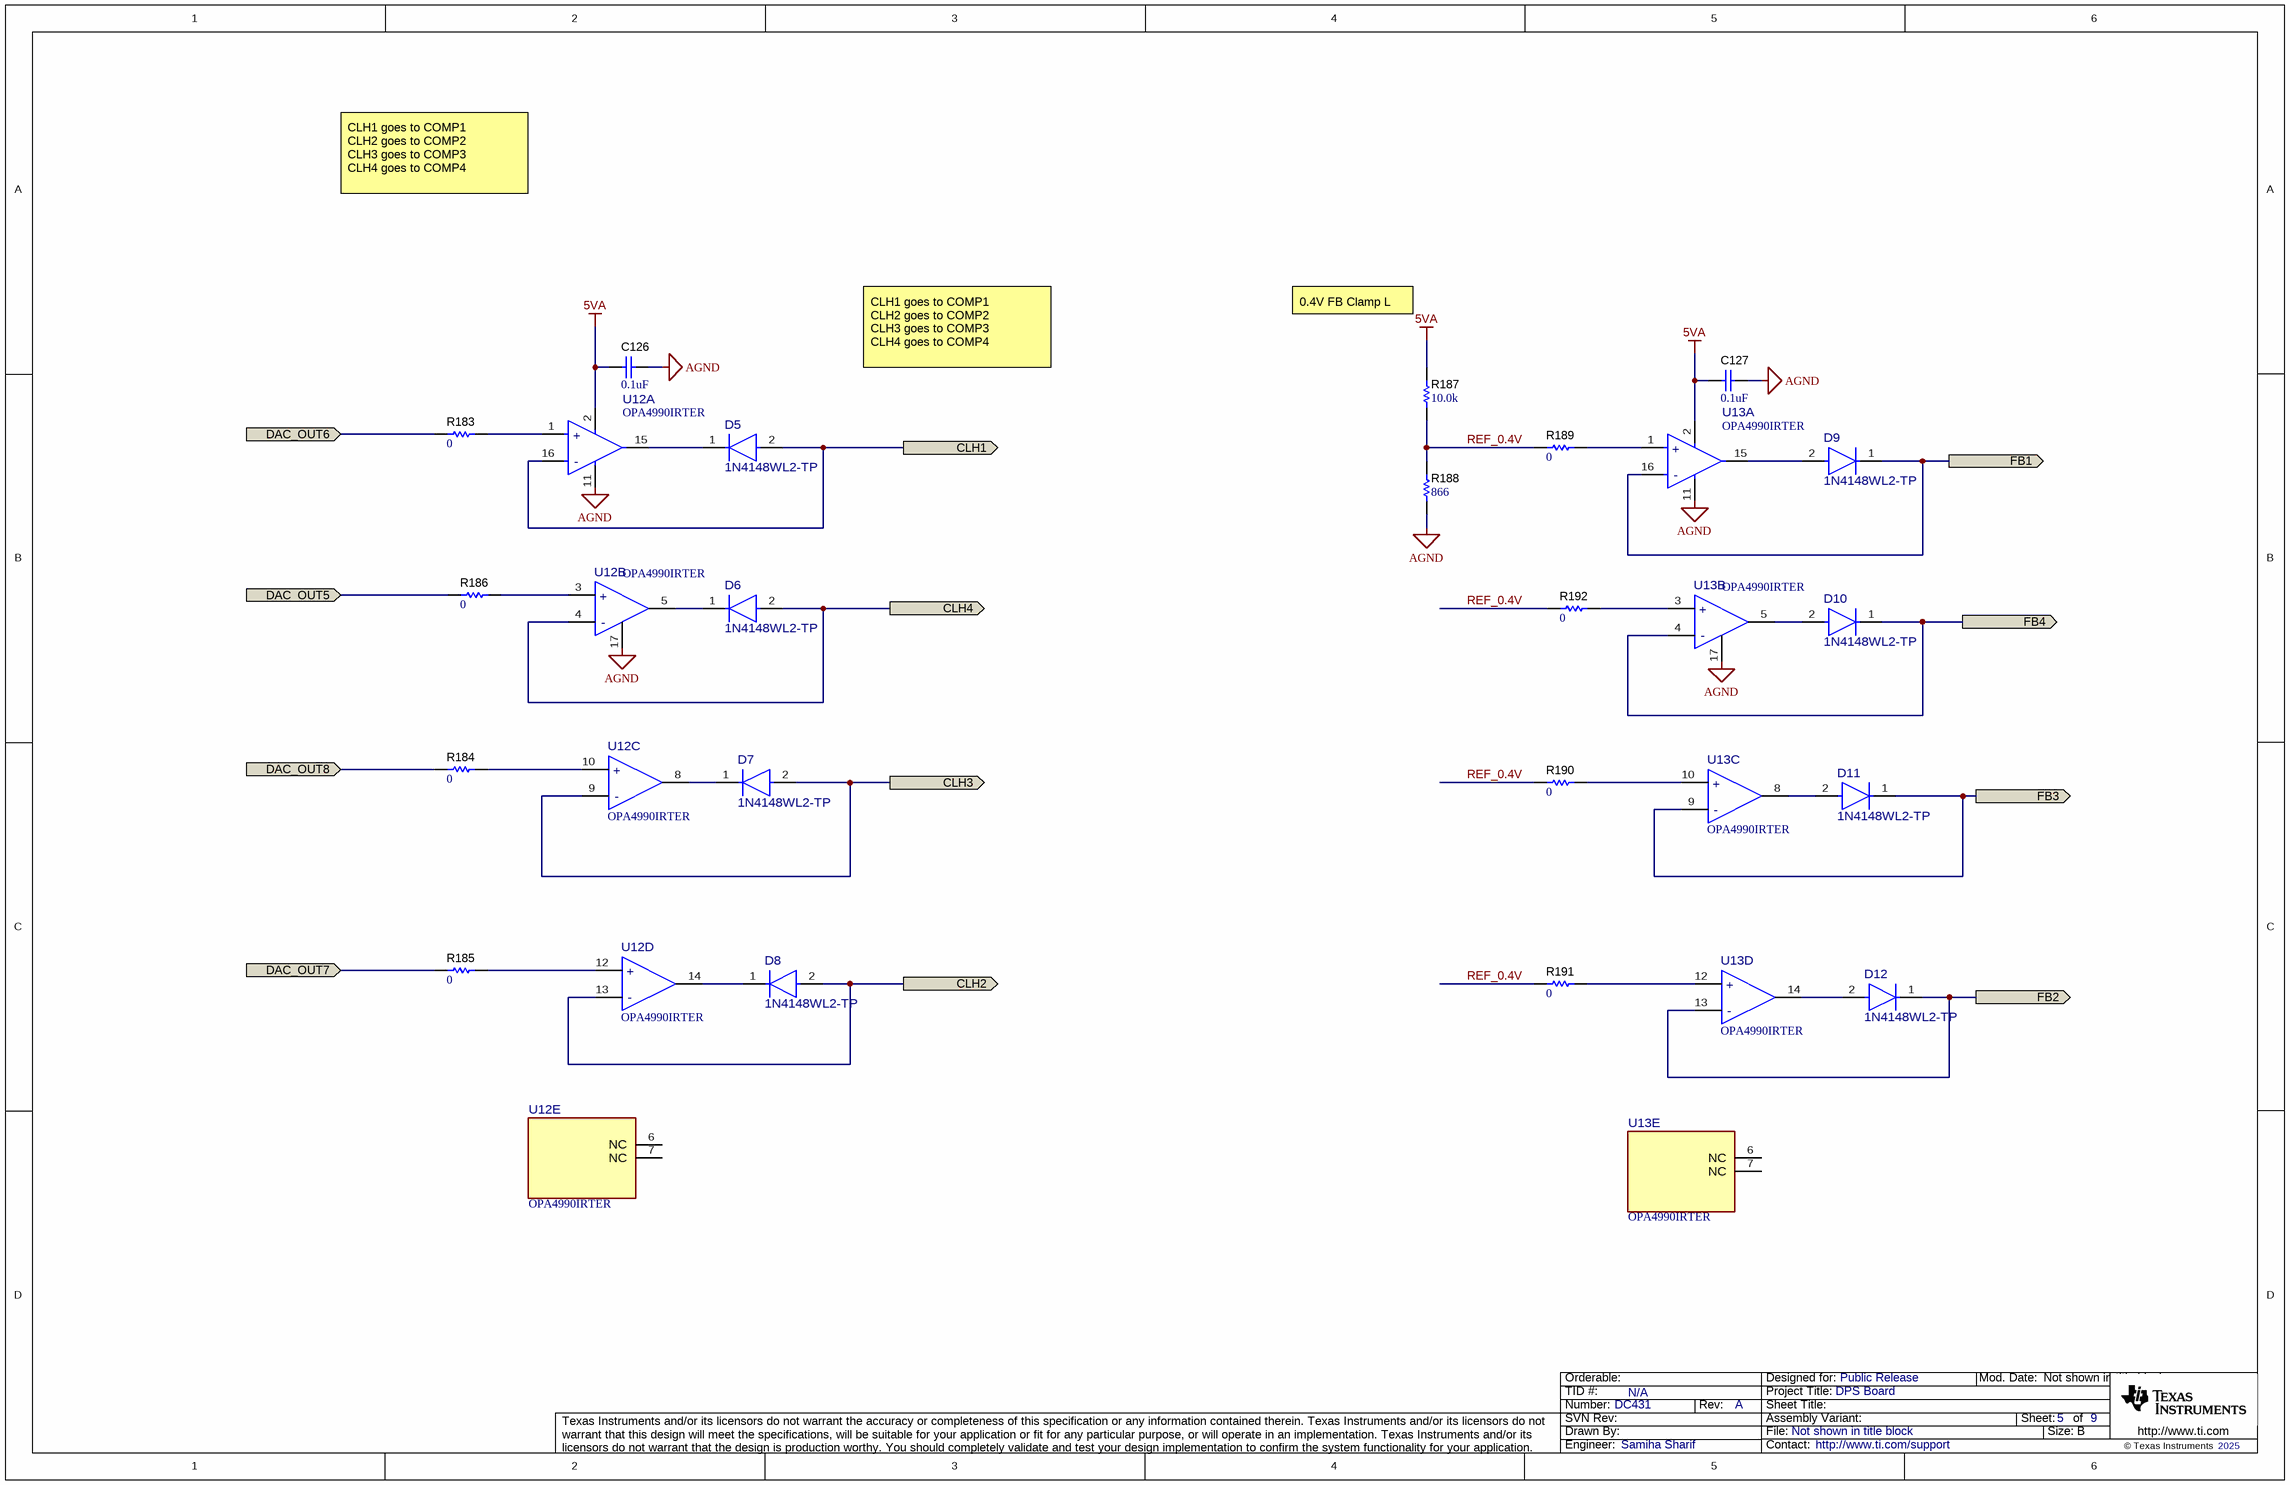
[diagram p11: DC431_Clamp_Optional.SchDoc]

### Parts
C126  ValueDisplayed: 0.1uF  [0402S]  (hidden comment: GRM155R61C104KA88D)
C127  ValueDisplayed: 0.1uF  [0402S]  (hidden comment: GRM155R61C104KA88D)
D5  1N4148WL2-TP  [FP-1N4148WL2-TP_DFN1006-MFG]
D6  1N4148WL2-TP  [FP-1N4148WL2-TP_DFN1006-MFG]
D7  1N4148WL2-TP  [FP-1N4148WL2-TP_DFN1006-MFG]
D8  1N4148WL2-TP  [FP-1N4148WL2-TP_DFN1006-MFG]
D9  1N4148WL2-TP  [FP-1N4148WL2-TP_DFN1006-MFG]
D10  1N4148WL2-TP  [FP-1N4148WL2-TP_DFN1006-MFG]
D11  1N4148WL2-TP  [FP-1N4148WL2-TP_DFN1006-MFG]
D12  1N4148WL2-TP  [FP-1N4148WL2-TP_DFN1006-MFG]
R183  ValueDisplayed: 0  [0402S]  (hidden comment: CRCW04020000Z0ED)
R184  ValueDisplayed: 0  [0402S]  (hidden comment: CRCW04020000Z0ED)
R185  ValueDisplayed: 0  [0402S]  (hidden comment: CRCW04020000Z0ED)
R186  ValueDisplayed: 0  [0402S]  (hidden comment: CRCW04020000Z0ED)
R187  ValueDisplayed: 10.0k  [0603S]  (hidden comment: RT0603BRD0710KL)
R188  ValueDisplayed: 866  [0402S]  (hidden comment: CRCW0402866RFKED)
R189  ValueDisplayed: 0  [0402S]  (hidden comment: CRCW04020000Z0ED)
R190  ValueDisplayed: 0  [0402S]  (hidden comment: CRCW04020000Z0ED)
R191  ValueDisplayed: 0  [0402S]  (hidden comment: CRCW04020000Z0ED)
R192  ValueDisplayed: 0  [0402S]  (hidden comment: CRCW04020000Z0ED)
U12  OPA4990IRTER  [RTE0016C-MFG]  (parts A,B,C,D,E of 5)
U13  OPA4990IRTER  [RTE0016C-MFG]  (parts A,B,C,D,E of 5)

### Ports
CLH1 (out), CLH2 (out), CLH3 (out), CLH4 (out), DAC_OUT5 (in), DAC_OUT6 (in), DAC_OUT7 (in), DAC_OUT8 (in), FB1 (out), FB2 (out), FB3 (out), FB4 (out)

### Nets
5VA: C126.2 C127.2 R187.1 U12.2(V+) U13.2(V+)
AGND: C126.1 C127.1 R188.1 U12.11(V-) U12.17(Thermal_Pad) U13.11(V-) U13.17(Thermal_Pad)
COMP1: D5.2(Anode) U12.16(IN1-) ; port CLH1
COMP2: D8.2(Anode) U12.13(IN4-) ; port CLH2
COMP3: D7.2(Anode) U12.9(IN3-) ; port CLH3
COMP4: D6.2(Anode) U12.4(IN2-) ; port CLH4
DAC_OUT5: R186.2 ; port DAC_OUT5
DAC_OUT6: R183.2 ; port DAC_OUT6
DAC_OUT7: R185.2 ; port DAC_OUT7
DAC_OUT8: R184.2 ; port DAC_OUT8
FB1: D9.1(Cathode) U13.16(IN1-) ; port FB1
FB2: D12.1(Cathode) U13.13(IN4-) ; port FB2
FB3: D11.1(Cathode) U13.9(IN3-) ; port FB3
FB4: D10.1(Cathode) U13.4(IN2-) ; port FB4
REF_0.4V: R187.2 R188.2 R189.2 R190.2 R191.2 R192.2
NetD5_1: D5.1(Cathode) U12.15(OUT1)
NetD6_1: D6.1(Cathode) U12.5(OUT2)
NetD7_1: D7.1(Cathode) U12.8(OUT3)
NetD8_1: D8.1(Cathode) U12.14(OUT4)
NetD9_2: D9.2(Anode) U13.15(OUT1)
NetD10_2: D10.2(Anode) U13.5(OUT2)
NetD11_2: D11.2(Anode) U13.8(OUT3)
NetD12_2: D12.2(Anode) U13.14(OUT4)
NetR183_1: R183.1 U12.1(IN1+)
NetR184_1: R184.1 U12.10(IN3+)
NetR185_1: R185.1 U12.12(IN4+)
NetR186_1: R186.1 U12.3(IN2+)
NetR189_1: R189.1 U13.1(IN1+)
NetR190_1: R190.1 U13.10(IN3+)
NetR191_1: R191.1 U13.12(IN4+)
NetR192_1: R192.1 U13.3(IN2+)

Not connected (* = marked no-connect by the designer): U12 6(NC) 7(NC); U13 6(NC) 7(NC)

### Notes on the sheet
- CLH1 goes to COMP1
  CLH2 goes to COMP2
  CLH3 goes to COMP3
  CLH4 goes to COMP4
- 0.4V FB Clamp L

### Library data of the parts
C126 C127 = CMP-0006591-2: CAP, CERM, 0.1 uF, 16 V, +/- 10%, X5R, 0402; Manufacturer: MuRata; TaMin_C: -55°C; Polarized: N; SizeAreaWB_mm2: 3; Value1: Unknown; U/M: EA; Value: 0.1uF; TaMax_C: 85°C; SizeZ_mm: 0.6; SizeX_mm: 1; SizeY_mm: 0.5; Cap_Case: 0402; Value2: 16V; Cap_F: 100nF; AEC Category: Q200
D5-D12 = CMP-0126888-1: Diode Switching 100V 0.15A 2-Pin DFN T/R; Manufacturer: MCC; TJmax_C: 150°C; AEC Qualified: No; SizeZ_mm: 0.5mm; Cap_F: 1.5pF; Forward Current: 150mA; Max Surge Forward Current: 4A; Peak Reverse Current: 5uA
R183-R186 R189-R192 = CMP-0026822-3: as R22-R25 on sheet DC431_PowerStage
R187 = CMP-0023653-3: as R5 on sheet DC431_PowerStage
R188 = CMP-0026581-2: RES, 866, 1%, 0.063 W, AEC-Q200 Grade 0, 0402; Manufacturer: Vishay-Dale; Power_W: 63mW; TempCo: 100 ppm/C; Value_Code: 866R; Value: 866; EIA_Code: E96; SizeX_mm: 1; SizeY_mm: 0.5; SizeZ_mm: 0.6; Value2: 0.063W; AEC Qualified: Y; VDC_V: 50V; AEC Category: Q200; AEC Grade: 0
U12 U13 = CMP-0123533-1: Quad 1-MHz, 40-V rail-to-rail input/output, low-offset-voltage, low-power op amp 16-WQFN -40 to 125; Manufacturer: Texas Instruments; SizeZ_mm: 0.8mm; AEC Qualified: No; Gain Bandwidth: 1.1MHz; Input Bias Current: 10pA; Input Offset Voltage: 0.3mV; Max Dual Supply Voltage: 20V; Max Supply Voltage: 40V; Min Dual Supply Voltage: 1.35V; Min Supply Voltage: 2.7V; Nominal Supply Current: 120uA; Number Of Channels: 4; Output Current Per Channel: 80mA; Response Time: 5us; Standoff Height: 0mm; TJmax_C: +150°C; Voltage Gain: 145dB

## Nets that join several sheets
1V8A: DC431_BiasPower (C108.1 R115.2 TP32.1 U10.5), DC431_ADC (6 pins)
3V3D: DC431_BiasPower (C103.1 R111.2 TP31.1 U9.5), DC431_Relay (R179.2 R180.2 R181.2 R182.2), DC431_ADC (11 pins), DC431_Controller (R178.2)
5V2: DC431_BiasPower (5 pins), DC431_ADC (R102.2), DC431_Controller (10 pins)
5VA: DC431_BiasPower (9 pins), DC431_ADC (13 pins), DC431_Controller (C109.2 U11.4), DC431_Clamp_Optional (5 pins)
-5V: DC431_BiasPower (C101.2 TP30.1 U7.2), DC431_ADC (R89.2 R106.2)
AGND: DC431_TopLevel (TP38.1), DC431_BiasPower (21 pins), DC431_Relay (Q1.2 Q2.2 Q7.2 Q8.2), DC431_ADC (44 pins), DC431_Controller (36 pins), DC431_PowerStage (24 pins), DC431_Clamp_Optional (7 pins)
PGND: DC431_TopLevel (5 pins), DC431_BiasPower (9 pins), DC431_Relay (16 pins), DC431_PowerStage (98 pins)
ADC_CONVST: DC431_ADC (R83.2), DC431_Controller (R139.2 R156.1)
ADC_CSn: DC431_ADC (R79.2 R88.1 TP25.1), DC431_Controller (R123.1 R126.1 R157.1)
ADC_DRDY: DC431_ADC (R82.2), DC431_Controller (R127.1 R159.1)
ADC_RSTn: DC431_ADC (R84.2), DC431_Controller (R128.1 R160.1)
ADC_SCLK: DC431_ADC (R76.2 TP22.1), DC431_Controller (R122.1 R125.1 R158.1)
ADC_SDI: DC431_ADC (R77.2 TP23.1), DC431_Controller (R120.1 R155.1)
ADC_SDOA: DC431_ADC (R78.2 R81.2 TP24.1), DC431_Controller (R121.1 R161.1)
ADC_SDOB: DC431_ADC (R80.2), DC431_Controller (R124.1 R162.1)
AINM1: DC431_Relay (J8.3), DC431_ADC (U3.58)
AINM2: DC431_Relay (J9.1), DC431_ADC (U3.60)
AINM3: DC431_Relay (J14.3), DC431_ADC (U3.62)
AINM4: DC431_ADC (U3.64), DC431_PowerStage (R62.2 R63.2)
AINM5: DC431_ADC (U3.2), DC431_PowerStage (C64.1 R6.2 R41.1)
AINM6: DC431_ADC (U3.4), DC431_PowerStage (C65.1 R12.2 R53.1)
AINM7: DC431_ADC (U3.6), DC431_PowerStage (C66.1 R15.2 R57.1)
AINM8: DC431_ADC (U3.8), DC431_PowerStage (R44.2 R45.2)
AINM9: DC431_ADC (U3.10), DC431_PowerStage (R70.2 TP18.1)
AINM10: DC431_ADC (U3.12), DC431_PowerStage (R71.2 TP19.1)
AINM11: DC431_ADC (U3.14), DC431_PowerStage (R72.2 TP20.1)
AINM12: DC431_ADC (U3.16), DC431_PowerStage (R48.2 R49.2)
AINP1: DC431_Relay (J8.1), DC431_ADC (U3.57)
AINP2: DC431_Relay (J9.3), DC431_ADC (U3.59)
AINP3: DC431_Relay (J14.1), DC431_ADC (U3.61)
AINP4: DC431_ADC (U3.63), DC431_PowerStage (R60.2 R61.2)
AINP5: DC431_ADC (U3.1), DC431_PowerStage (C64.2 R5.2 R31.1)
AINP6: DC431_ADC (U3.3), DC431_PowerStage (C65.2 R11.2 R37.1)
AINP7: DC431_ADC (U3.5), DC431_PowerStage (C66.2 R14.2 R54.1)
AINP8: DC431_ADC (U3.7), DC431_PowerStage (R42.2 R43.2)
AINP9: DC431_ADC (U3.9), DC431_PowerStage (R24.2 TP14.1)
AINP10: DC431_ADC (U3.11), DC431_PowerStage (R25.2 TP16.1)
AINP11: DC431_ADC (U3.13), DC431_PowerStage (R22.2 TP15.1)
AINP12: DC431_ADC (U3.15), DC431_PowerStage (R46.2 R47.2)
COMP1: DC431_PowerStage (R3.2 U1.A12), DC431_Clamp_Optional (D5.2 U12.16)
COMP2: DC431_PowerStage (R9.2 U1.A10), DC431_Clamp_Optional (D8.2 U12.13)
COMP3: DC431_PowerStage (R4.2 U1.A5), DC431_Clamp_Optional (D7.2 U12.9)
COMP4: DC431_PowerStage (R10.2 U1.A3), DC431_Clamp_Optional (D6.2 U12.4)
DAC_CH4: DC431_ADC (R90.1 U5.3), DC431_PowerStage (R36.2)
DAC_CSn: DC431_ADC (U4.12), DC431_Controller (R145.2 R152.1)
DAC_OUT1: DC431_ADC (R93.1), DC431_PowerStage (R28.2)
DAC_OUT2: DC431_ADC (R92.1), DC431_PowerStage (R34.2)
DAC_OUT3: DC431_ADC (R91.1), DC431_PowerStage (R52.2)
DAC_OUT5: DC431_ADC (R94.1), DC431_PowerStage (R51.2), DC431_Clamp_Optional (R186.2)
DAC_OUT6: DC431_ADC (R95.1), DC431_Clamp_Optional (R183.2)
DAC_OUT7: DC431_ADC (R96.1), DC431_Clamp_Optional (R185.2)
DAC_OUT8: DC431_ADC (R97.1), DC431_Clamp_Optional (R184.2)
DAC_OUT_BI4: DC431_ADC (R101.2 U5.1), DC431_PowerStage (R50.2)
DAC_SCLK: DC431_ADC (U4.13), DC431_Controller (R144.2 R151.1)
DAC_SDI: DC431_ADC (U4.14), DC431_Controller (R142.2 R154.1)
DAC_SDO: DC431_ADC (U4.15), DC431_Controller (R143.2 R163.1)
EN_DCDC1: DC431_Controller (R129.1 R149.1), DC431_PowerStage (U1.E14)
EN_DCDC2: DC431_Controller (R130.1 R150.1), DC431_PowerStage (U1.E8)
EN_DCDC3: DC431_Controller (R131.1 R164.1), DC431_PowerStage (U1.E7)
EN_DCDC4: DC431_Controller (R132.1 R170.2 R177.2 R178.1), DC431_PowerStage (R64.2 R65.2)
EN_RLY1: DC431_Relay (Q1.1), DC431_Controller (R133.1 R165.1)
EN_RLY2: DC431_Relay (Q2.1), DC431_Controller (R134.1 R166.1)
EN_RLY3: DC431_Relay (Q7.1), DC431_Controller (R135.1 R167.1)
EN_RLY4: DC431_Relay (Q8.1), DC431_PowerStage (R68.1)
EN_RLY4_H: DC431_Controller (R136.1 R168.1), DC431_PowerStage (R68.2 R69.2)
EPWM_EX_1: DC431_Controller (R119.1 R174.2), DC431_PowerStage (J1.4)
EPWM_EX_2: DC431_Controller (R140.2 R175.2), DC431_PowerStage (J1.6)
EPWM_EX_3: DC431_Controller (R141.2 R176.2), DC431_PowerStage (J1.8)
FB1: DC431_PowerStage (R26.1 R27.2 R28.1 U1.A13), DC431_Clamp_Optional (D9.1 U13.16)
FB2: DC431_PowerStage (R29.1 R30.2 R34.1 U1.A9), DC431_Clamp_Optional (D12.1 U13.13)
FB3: DC431_PowerStage (R38.2 R39.1 R52.1 U1.A6), DC431_Clamp_Optional (D11.1 U13.9)
FB4: DC431_PowerStage (R32.1 R33.2 R36.1 U1.A2), DC431_Clamp_Optional (D10.1 U13.4)
RELAY_IN1: DC431_Relay (Q6.7 Q6.8 Q6.9), DC431_PowerStage (R35.2 R41.2)
RELAY_IN2: DC431_Relay (Q5.7 Q5.8 Q5.9), DC431_PowerStage (R40.2 R53.2)
RELAY_IN3: DC431_Relay (Q11.7 Q11.8 Q11.9), DC431_PowerStage (R55.2 R57.2)
RELAY_IN4: DC431_Relay (Q12.7 Q12.8 Q12.9), DC431_PowerStage (R58.2 R59.2)
REMSN4: DC431_Relay (J15.1), DC431_PowerStage (R62.1)
REMSP4: DC431_Relay (J15.3), DC431_PowerStage (R60.1)
SYNC_DCDC: DC431_Controller (R138.2 R153.1), DC431_PowerStage (R66.2 R67.2)
SYNC_EX_2: DC431_Controller (R116.1 R171.2), DC431_PowerStage (J1.7)
SYNC_EX_3: DC431_Controller (R117.1 R172.2), DC431_PowerStage (J1.9)
SYNC_EX_4: DC431_Controller (R118.1 R173.2), DC431_PowerStage (J1.2)
V_HV: DC431_TopLevel (C124.1 C125.1 J20.1 J21.1), DC431_BiasPower (J3.3), DC431_ADC (R103.2), DC431_Controller (R146.2), DC431_PowerStage (27 pins)

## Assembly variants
001(1+1+1+1): not fitted C70 C83 LBL1 R43 R45 R47 R49 R50 R51 R61 R63 R65 R67 R69 R80 R81 R85 R86 R88 R98 R102 R103 R104 R105 R106 R111 R148 R149 R150 R151 R152 R153 R154 R155 R156 R157 R158 R159 R160 R161 R162 R163 R164 R165 R166 R167 R169 R170 R171 R172 R173 R174 R175 R176 R177 U5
